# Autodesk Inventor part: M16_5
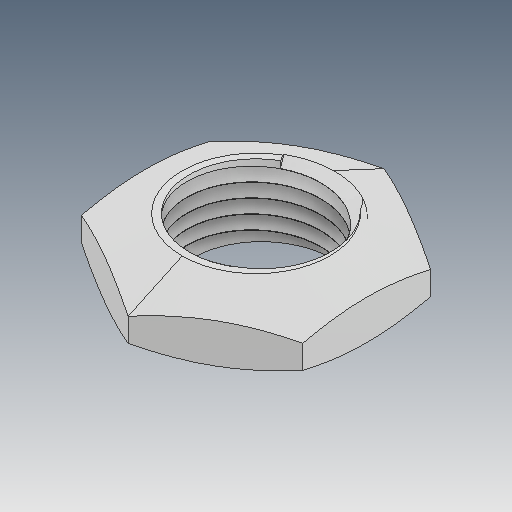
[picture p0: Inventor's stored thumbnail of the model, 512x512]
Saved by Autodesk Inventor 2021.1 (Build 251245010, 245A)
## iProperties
Created: 2021-05
Part Number: M16_5
Material: Ogólny
Document SubType Name: Modeling
Designer: user
Density: 1 g/cm^3
Appearance: Domyślna
Author: user
Revision Number: ÈÎºÎ
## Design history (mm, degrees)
feature "ÊäÈë1"
node "Bryła1"
